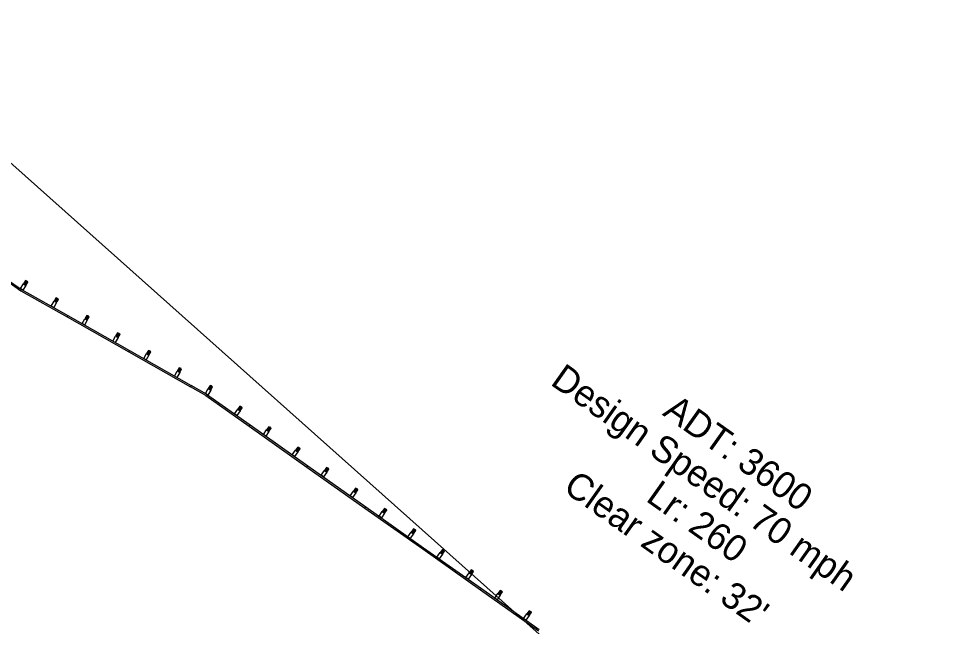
# Model space of a CAD drawing. Extents: x 16457860 to 16462445, y 6896068 to 6900243.
# Drawn here: x 16461488.7 to 16461654.4, y 6896924.5 to 6897031.7 of the extents above; entities that cross this region are included whole.
import ezdxf

# ---------------------------------------------------------------- set-up
doc = ezdxf.new("R2010")
doc.units = 0
doc.layers.add('Cell', color=7, linetype='Continuous')
doc.layers.add('Draft_DNC', color=7, linetype='Continuous')

msp = doc.modelspace()

# ---------------------------------------------------------------- linework, layer by layer
at = {"layer": 'Cell'}
for p, q in [((16461486.51, 6896985.45), (16461489.06, 6896983.65)), ((16461486.66, 6896985.67), (16461489.19, 6896983.89)), ((16461489.74, 6896984.75), (16461490.1, 6896985.31)), ((16461489.88, 6896985.44), (16461489.95, 6896984.61)), ((16461490.15, 6896985.39), (16461490.15, 6896985.4)), ((16461488.99, 6896984.03), (16461489.53, 6896984.88)), ((16461489.41, 6896983.76), (16461488.99, 6896984.03)), ((16461489.06, 6896983.65), (16461497.22, 6896979.03)), ((16461489.19, 6896983.89), (16461497.35, 6896979.27)), ((16461489.95, 6896984.61), (16461489.41, 6896983.76)), ((16461490.31, 6896985.18), (16461489.53, 6896984.88)), ((16461489.53, 6896984.88), (16461489.95, 6896984.61)), ((16461495.67, 6896982.14), (16461494.91, 6896981.8)), ((16461495.12, 6896981.68), (16461495.46, 6896982.26)), ((16461495.24, 6896982.38), (16461495.34, 6896981.56)), ((16461495.5, 6896982.35), (16461495.51, 6896982.35)), ((16461494.41, 6896980.93), (16461494.91, 6896981.8)), ((16461494.85, 6896980.68), (16461494.41, 6896980.93)), ((16461495.34, 6896981.56), (16461494.85, 6896980.68)), ((16461494.91, 6896981.8), (16461495.34, 6896981.56)), ((16461497.22, 6896979.03), (16461497.35, 6896979.27)), ((16461497.22, 6896979.03), (16461497.35, 6896979.27)), ((16461497.22, 6896979.03), (16461497.35, 6896979.27)), ((16461497.22, 6896979.03), (16461508.09, 6896972.87)), ((16461497.35, 6896979.27), (16461508.22, 6896973.1)), ((16461499.85, 6896977.85), (16461500.34, 6896978.72)), ((16461501.11, 6896979.05), (16461500.34, 6896978.72)), ((16461500.34, 6896978.72), (16461500.78, 6896978.47)), ((16461500.56, 6896978.6), (16461500.89, 6896979.18)), ((16461500.67, 6896979.3), (16461500.78, 6896978.47)), ((16461500.94, 6896979.26), (16461500.94, 6896979.27)), ((16461500.29, 6896977.6), (16461499.85, 6896977.85)), ((16461500.78, 6896978.47), (16461500.29, 6896977.6)), ((16461505.29, 6896974.77), (16461505.78, 6896975.64)), ((16461506.22, 6896975.39), (16461505.72, 6896974.52)), ((16461506.55, 6896975.97), (16461505.78, 6896975.64)), ((16461505.78, 6896975.64), (16461506.22, 6896975.39)), ((16461506, 6896975.52), (16461506.33, 6896976.1)), ((16461506.11, 6896976.22), (16461506.22, 6896975.39)), ((16461506.38, 6896976.18), (16461506.38, 6896976.19)), ((16461505.72, 6896974.52), (16461505.29, 6896974.77)), ((16461508.09, 6896972.87), (16461508.22, 6896973.1)), ((16461508.09, 6896972.87), (16461508.22, 6896973.1)), ((16461508.09, 6896972.87), (16461518.97, 6896966.7)), ((16461508.22, 6896973.1), (16461519.1, 6896966.94)), ((16461510.73, 6896971.69), (16461511.22, 6896972.56)), ((16461511.65, 6896972.31), (16461511.16, 6896971.44)), ((16461511.98, 6896972.89), (16461511.22, 6896972.56)), ((16461511.22, 6896972.56), (16461511.65, 6896972.31)), ((16461511.44, 6896972.43), (16461511.76, 6896973.01)), ((16461511.55, 6896973.14), (16461511.65, 6896972.31)), ((16461511.81, 6896973.1), (16461511.82, 6896973.1)), ((16461511.16, 6896971.44), (16461510.73, 6896971.69)), ((16461516.16, 6896968.6), (16461516.66, 6896969.48)), ((16461517.09, 6896969.23), (16461516.6, 6896968.36)), ((16461517.42, 6896969.81), (16461516.66, 6896969.48)), ((16461516.66, 6896969.48), (16461517.09, 6896969.23)), ((16461516.87, 6896969.35), (16461517.2, 6896969.93)), ((16461516.98, 6896970.06), (16461517.09, 6896969.23)), ((16461517.25, 6896970.02), (16461517.25, 6896970.02)), ((16461516.6, 6896968.36), (16461516.16, 6896968.6)), ((16461518.97, 6896966.7), (16461519.1, 6896966.94)), ((16461518.97, 6896966.7), (16461519.1, 6896966.94)), ((16461521.68, 6896965.16), (16461518.97, 6896966.7)), ((16461521.84, 6896965.39), (16461519.1, 6896966.94)), ((16461521.62, 6896965.51), (16461522.12, 6896966.38)), ((16461522.06, 6896965.26), (16461521.62, 6896965.51)), ((16461521.84, 6896965.39), (16461529.49, 6896959.97)), ((16461522.55, 6896966.13), (16461522.06, 6896965.26)), ((16461522.88, 6896966.71), (16461522.12, 6896966.38)), ((16461522.12, 6896966.38), (16461522.55, 6896966.13)), ((16461522.33, 6896966.26), (16461522.12, 6896966.38)), ((16461522.33, 6896966.26), (16461522.12, 6896966.38)), ((16461522.33, 6896966.26), (16461522.66, 6896966.84)), ((16461522.45, 6896966.96), (16461522.55, 6896966.13)), ((16461522.71, 6896966.92), (16461522.71, 6896966.93)), ((16461521.68, 6896965.16), (16461529.34, 6896959.75)), ((16461526.74, 6896961.92), (16461527.32, 6896962.74)), ((16461527.73, 6896962.45), (16461527.15, 6896961.63)), ((16461528.11, 6896962.99), (16461527.32, 6896962.74)), ((16461527.32, 6896962.74), (16461527.73, 6896962.45)), ((16461527.52, 6896962.59), (16461527.91, 6896963.14)), ((16461527.7, 6896963.28), (16461527.73, 6896962.45)), ((16461527.96, 6896963.22), (16461527.97, 6896963.22)), ((16461527.15, 6896961.63), (16461526.74, 6896961.92)), ((16461529.34, 6896959.75), (16461529.49, 6896959.97)), ((16461529.34, 6896959.75), (16461529.49, 6896959.97)), ((16461529.34, 6896959.75), (16461539.54, 6896952.53)), ((16461529.49, 6896959.97), (16461539.7, 6896952.75)), ((16461531.84, 6896958.31), (16461532.42, 6896959.13)), ((16461532.83, 6896958.84), (16461532.25, 6896958.02)), ((16461533.21, 6896959.38), (16461532.42, 6896959.13)), ((16461532.42, 6896959.13), (16461532.83, 6896958.84)), ((16461532.62, 6896958.98), (16461533.01, 6896959.53)), ((16461532.8, 6896959.67), (16461532.83, 6896958.84)), ((16461533.06, 6896959.61), (16461533.07, 6896959.61)), ((16461532.25, 6896958.02), (16461531.84, 6896958.31)), ((16461536.94, 6896954.7), (16461537.52, 6896955.52)), ((16461538.31, 6896955.77), (16461537.52, 6896955.52)), ((16461537.52, 6896955.52), (16461537.93, 6896955.23)), ((16461537.73, 6896955.37), (16461538.11, 6896955.92)), ((16461537.91, 6896956.06), (16461537.93, 6896955.23)), ((16461538.17, 6896956), (16461538.17, 6896956)), ((16461537.35, 6896954.41), (16461536.94, 6896954.7)), ((16461537.93, 6896955.23), (16461537.35, 6896954.41)), ((16461539.54, 6896952.53), (16461539.7, 6896952.75)), ((16461539.54, 6896952.53), (16461539.7, 6896952.75)), ((16461539.54, 6896952.53), (16461549.75, 6896945.31)), ((16461539.7, 6896952.75), (16461549.9, 6896945.53)), ((16461543.42, 6896952.16), (16461542.62, 6896951.91)), ((16461542.83, 6896951.76), (16461543.21, 6896952.31)), ((16461543.01, 6896952.45), (16461543.03, 6896951.62)), ((16461543.27, 6896952.39), (16461543.27, 6896952.39)), ((16461542.05, 6896951.09), (16461542.62, 6896951.91)), ((16461542.45, 6896950.8), (16461542.05, 6896951.09)), ((16461543.03, 6896951.62), (16461542.45, 6896950.8)), ((16461542.62, 6896951.91), (16461543.03, 6896951.62)), ((16461548.11, 6896948.84), (16461548.13, 6896948.01)), ((16461547.15, 6896947.48), (16461547.73, 6896948.3)), ((16461547.56, 6896947.19), (16461547.15, 6896947.48)), ((16461548.13, 6896948.01), (16461547.56, 6896947.19)), ((16461548.52, 6896948.55), (16461547.73, 6896948.3)), ((16461547.73, 6896948.3), (16461548.13, 6896948.01)), ((16461547.93, 6896948.15), (16461548.32, 6896948.7)), ((16461548.37, 6896948.78), (16461548.38, 6896948.78)), ((16461549.75, 6896945.31), (16461549.9, 6896945.53)), ((16461549.75, 6896945.31), (16461549.9, 6896945.53)), ((16461549.9, 6896945.53), (16461560.11, 6896938.31)), ((16461549.75, 6896945.31), (16461559.95, 6896938.09)), ((16461552.25, 6896943.87), (16461552.83, 6896944.69)), ((16461552.66, 6896943.58), (16461552.25, 6896943.87)), ((16461553.24, 6896944.4), (16461552.66, 6896943.58)), ((16461553.62, 6896944.94), (16461552.83, 6896944.69)), ((16461552.83, 6896944.69), (16461553.24, 6896944.4)), ((16461553.03, 6896944.54), (16461553.42, 6896945.09)), ((16461553.21, 6896945.23), (16461553.24, 6896944.4)), ((16461553.47, 6896945.17), (16461553.48, 6896945.17)), ((16461557.35, 6896940.26), (16461557.93, 6896941.08)), ((16461558.34, 6896940.79), (16461557.76, 6896939.97)), ((16461558.72, 6896941.33), (16461557.93, 6896941.08)), ((16461557.93, 6896941.08), (16461558.34, 6896940.79)), ((16461558.13, 6896940.93), (16461558.52, 6896941.48)), ((16461558.32, 6896941.62), (16461558.34, 6896940.79)), ((16461558.58, 6896941.56), (16461558.58, 6896941.56)), ((16461557.76, 6896939.97), (16461557.35, 6896940.26)), ((16461559.95, 6896938.09), (16461560.11, 6896938.31)), ((16461559.95, 6896938.09), (16461560.11, 6896938.31)), ((16461559.95, 6896938.09), (16461570.16, 6896930.87)), ((16461560.11, 6896938.31), (16461570.31, 6896931.09)), ((16461562.45, 6896936.65), (16461563.03, 6896937.47)), ((16461563.83, 6896937.72), (16461563.03, 6896937.47)), ((16461563.03, 6896937.47), (16461563.44, 6896937.18)), ((16461563.24, 6896937.32), (16461563.62, 6896937.87)), ((16461563.42, 6896938.01), (16461563.44, 6896937.18)), ((16461563.68, 6896937.95), (16461563.68, 6896937.95)), ((16461562.86, 6896936.36), (16461562.45, 6896936.65)), ((16461563.44, 6896937.18), (16461562.86, 6896936.36)), ((16461568.93, 6896934.11), (16461568.13, 6896933.86)), ((16461568.34, 6896933.72), (16461568.72, 6896934.26)), ((16461568.52, 6896934.4), (16461568.54, 6896933.57)), ((16461568.78, 6896934.34), (16461568.78, 6896934.34)), ((16461567.56, 6896933.04), (16461568.13, 6896933.86)), ((16461567.97, 6896932.75), (16461567.56, 6896933.04)), ((16461568.54, 6896933.57), (16461567.97, 6896932.75)), ((16461568.13, 6896933.86), (16461568.54, 6896933.57)), ((16461570.16, 6896930.87), (16461570.31, 6896931.09)), ((16461570.16, 6896930.87), (16461570.31, 6896931.09)), ((16461570.16, 6896930.87), (16461580.36, 6896923.65)), ((16461570.31, 6896931.09), (16461580.52, 6896923.87)), ((16461573.44, 6896930.11), (16461573.83, 6896930.65)), ((16461573.62, 6896930.79), (16461573.65, 6896929.96)), ((16461573.88, 6896930.73), (16461573.89, 6896930.73)), ((16461572.66, 6896929.43), (16461573.24, 6896930.25)), ((16461573.07, 6896929.14), (16461572.66, 6896929.43)), ((16461573.65, 6896929.96), (16461573.07, 6896929.14)), ((16461574.03, 6896930.51), (16461573.24, 6896930.25)), ((16461573.24, 6896930.25), (16461573.65, 6896929.96)), ((16461577.76, 6896925.82), (16461578.34, 6896926.64)), ((16461578.17, 6896925.53), (16461577.76, 6896925.82)), ((16461578.75, 6896926.35), (16461578.17, 6896925.53)), ((16461579.13, 6896926.9), (16461578.34, 6896926.64)), ((16461578.34, 6896926.64), (16461578.75, 6896926.35)), ((16461578.54, 6896926.5), (16461578.93, 6896927.04)), ((16461578.72, 6896927.18), (16461578.75, 6896926.35)), ((16461578.98, 6896927.12), (16461578.99, 6896927.12))]:
    msp.add_line(p, q, dxfattribs=at)
for points in [[(16461489.53, 6896984.88), (16461489.95, 6896984.61), (16461490.31, 6896985.18), (16461489.88, 6896985.44)], [(16461494.91, 6896981.8), (16461495.34, 6896981.56), (16461495.67, 6896982.14), (16461495.24, 6896982.38)], [(16461500.34, 6896978.72), (16461500.78, 6896978.47), (16461501.11, 6896979.05), (16461500.67, 6896979.3)], [(16461505.78, 6896975.64), (16461506.22, 6896975.39), (16461506.55, 6896975.97), (16461506.11, 6896976.22)], [(16461511.22, 6896972.56), (16461511.65, 6896972.31), (16461511.98, 6896972.89), (16461511.55, 6896973.14)], [(16461516.66, 6896969.48), (16461517.09, 6896969.23), (16461517.42, 6896969.81), (16461516.98, 6896970.06)], [(16461522.12, 6896966.38), (16461522.55, 6896966.13), (16461522.88, 6896966.71), (16461522.45, 6896966.96)], [(16461527.32, 6896962.74), (16461527.73, 6896962.45), (16461528.11, 6896962.99), (16461527.7, 6896963.28)], [(16461532.42, 6896959.13), (16461532.83, 6896958.84), (16461533.21, 6896959.38), (16461532.8, 6896959.67)], [(16461537.52, 6896955.52), (16461537.93, 6896955.23), (16461538.31, 6896955.77), (16461537.91, 6896956.06)], [(16461542.62, 6896951.91), (16461543.03, 6896951.62), (16461543.42, 6896952.16), (16461543.01, 6896952.45)], [(16461547.73, 6896948.3), (16461548.13, 6896948.01), (16461548.52, 6896948.55), (16461548.11, 6896948.84)], [(16461552.83, 6896944.69), (16461553.24, 6896944.4), (16461553.62, 6896944.94), (16461553.21, 6896945.23)], [(16461557.93, 6896941.08), (16461558.34, 6896940.79), (16461558.72, 6896941.33), (16461558.32, 6896941.62)], [(16461563.03, 6896937.47), (16461563.44, 6896937.18), (16461563.83, 6896937.72), (16461563.42, 6896938.01)], [(16461568.13, 6896933.86), (16461568.54, 6896933.57), (16461568.93, 6896934.11), (16461568.52, 6896934.4)], [(16461573.24, 6896930.25), (16461573.65, 6896929.96), (16461574.03, 6896930.51), (16461573.62, 6896930.79)], [(16461578.34, 6896926.64), (16461578.75, 6896926.35), (16461579.13, 6896926.9), (16461578.72, 6896927.18)]]:
    msp.add_lwpolyline(points, close=True, dxfattribs=at)
for points in [[(16461490.07, 6896985.33), (16461490.09, 6896985.36), (16461490.15, 6896985.33), (16461490.12, 6896985.29)], [(16461490.1, 6896985.36), (16461490.13, 6896985.4), (16461490.16, 6896985.38), (16461490.14, 6896985.34)], [(16461489.74, 6896984.74), (16461489.53, 6896984.88), (16461489.53, 6896984.88)], [(16461495.43, 6896982.28), (16461495.45, 6896982.32), (16461495.51, 6896982.28), (16461495.48, 6896982.24)], [(16461495.46, 6896982.31), (16461495.49, 6896982.36), (16461495.52, 6896982.34), (16461495.49, 6896982.29)], [(16461500.86, 6896979.19), (16461500.88, 6896979.23), (16461500.94, 6896979.2), (16461500.92, 6896979.16)], [(16461500.89, 6896979.22), (16461500.92, 6896979.27), (16461500.96, 6896979.25), (16461500.93, 6896979.21)], [(16461506.3, 6896976.11), (16461506.32, 6896976.15), (16461506.38, 6896976.12), (16461506.36, 6896976.08)], [(16461506.33, 6896976.14), (16461506.36, 6896976.19), (16461506.39, 6896976.17), (16461506.37, 6896976.12)], [(16461511.74, 6896973.03), (16461511.76, 6896973.07), (16461511.82, 6896973.03), (16461511.79, 6896973)], [(16461511.77, 6896973.06), (16461511.8, 6896973.11), (16461511.83, 6896973.09), (16461511.8, 6896973.04)], [(16461517.17, 6896969.95), (16461517.19, 6896969.99), (16461517.25, 6896969.95), (16461517.23, 6896969.92)], [(16461517.21, 6896969.98), (16461517.23, 6896970.03), (16461517.27, 6896970.01), (16461517.24, 6896969.96)], [(16461522.63, 6896966.85), (16461522.66, 6896966.89), (16461522.71, 6896966.86), (16461522.69, 6896966.82)], [(16461522.67, 6896966.88), (16461522.69, 6896966.93), (16461522.73, 6896966.91), (16461522.7, 6896966.86)], [(16461527.88, 6896963.16), (16461527.9, 6896963.19), (16461527.96, 6896963.15), (16461527.93, 6896963.12)], [(16461527.92, 6896963.18), (16461527.95, 6896963.23), (16461527.98, 6896963.21), (16461527.95, 6896963.16)], [(16461532.98, 6896959.55), (16461533.01, 6896959.58), (16461533.06, 6896959.54), (16461533.04, 6896959.51)], [(16461533.02, 6896959.57), (16461533.05, 6896959.62), (16461533.08, 6896959.6), (16461533.05, 6896959.55)], [(16461538.08, 6896955.94), (16461538.11, 6896955.97), (16461538.16, 6896955.93), (16461538.14, 6896955.9)], [(16461538.12, 6896955.96), (16461538.15, 6896956.01), (16461538.18, 6896955.99), (16461538.15, 6896955.94)], [(16461543.19, 6896952.33), (16461543.21, 6896952.36), (16461543.27, 6896952.32), (16461543.24, 6896952.29)], [(16461543.22, 6896952.35), (16461543.25, 6896952.4), (16461543.28, 6896952.38), (16461543.25, 6896952.33)], [(16461548.29, 6896948.72), (16461548.31, 6896948.75), (16461548.37, 6896948.71), (16461548.34, 6896948.68)], [(16461548.32, 6896948.74), (16461548.36, 6896948.79), (16461548.39, 6896948.77), (16461548.36, 6896948.72)], [(16461553.39, 6896945.11), (16461553.42, 6896945.14), (16461553.47, 6896945.1), (16461553.44, 6896945.07)], [(16461553.43, 6896945.13), (16461553.46, 6896945.18), (16461553.49, 6896945.16), (16461553.46, 6896945.11)], [(16461558.49, 6896941.5), (16461558.52, 6896941.53), (16461558.57, 6896941.49), (16461558.55, 6896941.46)], [(16461558.53, 6896941.53), (16461558.56, 6896941.57), (16461558.59, 6896941.55), (16461558.56, 6896941.5)], [(16461563.59, 6896937.89), (16461563.62, 6896937.92), (16461563.67, 6896937.88), (16461563.65, 6896937.85)], [(16461563.63, 6896937.92), (16461563.66, 6896937.96), (16461563.69, 6896937.94), (16461563.66, 6896937.89)], [(16461568.7, 6896934.28), (16461568.72, 6896934.31), (16461568.78, 6896934.28), (16461568.75, 6896934.24)], [(16461568.73, 6896934.31), (16461568.76, 6896934.35), (16461568.8, 6896934.33), (16461568.76, 6896934.28)], [(16461573.8, 6896930.67), (16461573.82, 6896930.7), (16461573.88, 6896930.67), (16461573.85, 6896930.63)], [(16461573.84, 6896930.7), (16461573.87, 6896930.74), (16461573.9, 6896930.72), (16461573.87, 6896930.67)], [(16461578.9, 6896927.06), (16461578.93, 6896927.09), (16461578.98, 6896927.06), (16461578.96, 6896927.02)], [(16461578.94, 6896927.09), (16461578.97, 6896927.13), (16461579, 6896927.11), (16461578.97, 6896927.06)]]:
    msp.add_lwpolyline(points, dxfattribs=at)
at = {"layer": 'Draft_DNC'}
msp.add_line((16461458.68, 6897031.65), (16461654.44, 6896857.2), dxfattribs=at)

# ---------------------------------------------------------------- texts
for s, height, p in [('Design Speed: 70 mph', 4.6875, (16461582.3, 6896967.2)), ('ADT: 3600', 4.687, (16461602.1, 6896961.81)), ("Clear zone: 32'", 4.6875, (16461584.52, 6896948.41)), ('Lr: 260', 4.687, (16461599.14, 6896946.67))]:
    msp.add_text(s, height=height, rotation=324.7216, dxfattribs=at).set_placement(p)

doc.saveas('drawing.dxf')
